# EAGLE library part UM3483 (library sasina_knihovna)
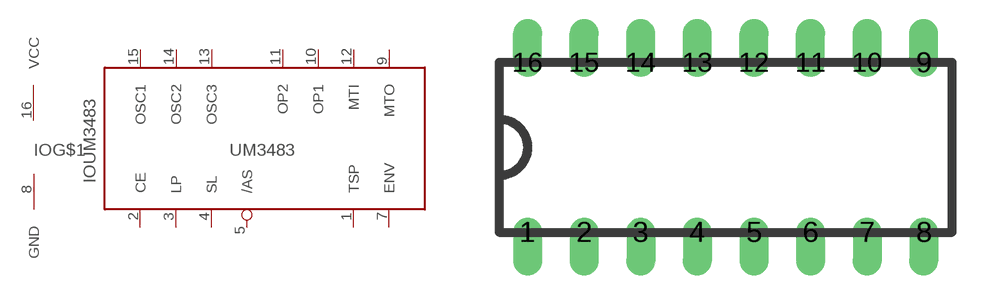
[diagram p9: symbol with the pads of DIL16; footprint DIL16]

Designator prefix IO; gates G$1=NAPAJENI UM3483=UM3483

## UM3483  [DIL16]
1  UM3483:TSP
2  UM3483:CE  in
3  UM3483:LP  in
4  UM3483:SL  in
5  UM3483:/AS  in
7  UM3483:ENV  pas
8  G$1:GND  pwr
9  UM3483:MTO  out
10  UM3483:OP1  out
11  UM3483:OP2  out
12  UM3483:MTI  in
13  UM3483:OSC3
14  UM3483:OSC2
15  UM3483:OSC1
16  G$1:VCC  pwr

## Footprint DIL16 (pad centres in mm)
drill 0.8 offset: 1 0,-1.27; 2 2.54,-1.27; 3 5.08,-1.27; 4 7.62,-1.27; 5 10.16,-1.27; 6 12.7,-1.27; 7 15.24,-1.27; 8 17.78,-1.27; 9 17.78,6.35; 10 15.24,6.35; 11 12.7,6.35; 12 10.16,6.35; 13 7.62,6.35; 14 5.08,6.35; 15 2.54,6.35; 16 0,6.35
